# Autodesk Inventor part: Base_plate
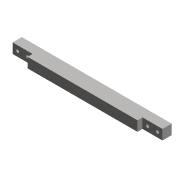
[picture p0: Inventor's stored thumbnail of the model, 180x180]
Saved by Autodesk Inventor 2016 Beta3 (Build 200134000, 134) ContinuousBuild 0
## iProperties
Created: 2016-02
Part Number: Base_plate
Material: Steel, Carbon
Document SubType Name: Modeling
Designer: Vertex
Density: 7.85 g/cm^3
Appearance: Semi-Polished
Mass: 1248.24 g
Surface Area: 308.183 cm^2
Volume: 159.012 cm^3
Author: Vertex
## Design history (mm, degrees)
sketch "Sketch1"
  geometry: L1 (0, 0)-(300, 0); L2 (300, 0)-(300, 20); L3 (300, 20)-(0, 20); L4 (0, 20)-(0, 0); L5 (0, 20)-(0, 0); L6 (40, 20)-(40, 0); L7 (300, 20)-(300, 0); L8 (260, 0)-(260, 20)
  constraints: 16 end point, 5 equal length, 1 horizontal, 1 perpendicular, 1 vertical
  dimensions: "d0" = 300 distance of L3.end L2.end; "d1" = 20 distance of L2.end L1.end; "d2" = 40 distance between parallel lines of L4 L6; "d3" = 40 distance between parallel lines of L2 L8
extrude "Extrusion1" new body sketch "Sketch1" distance "d4" = 20; taper "d5" = 0 deg
sketch "Sketch2"
  geometry: L1 (0, 0)-(300, 0); L2 (300, 0)-(300, 20); L3 (300, 20)-(0, 20); L4 (300, 20)-(0, 20) reference; L5 (0, 20)-(0, 0); L6 (0, 0)-(300, 0) reference; L7 (300, 20)-(300, 0); L8 (260, 0)-(260, 20); L9 (40, 20)-(40, 0)
  constraints: 8 end point, 4 point on line, 2 parallel, 1 perpendicular, 1 vertical
  dimensions: "d6" = 40 distance between parallel lines of L2 L8; "d7" = 40 distance between parallel lines of L5 L9
extrude "Extrusion2" join sketch "Sketch2" distance "d8" = 10; taper "d9" = 0 deg
workplane "Work Plane1"
chamfer "Chamfer1" distance "d28" = 1.5; stored, may be unused: second distance "d29" = 1.25, angle "d30" = 45 deg
hole "Hole3" diameter "d33" = 6; stored, may be unused: countersink angle "d37" = 90 deg, drill point angle "d39" = 118 deg; dims "d31" = 10, "d32" = 10, "d34" = 7.5, "d35" = 10, "d36" = 10, "d38" = 10
hole "Hole4" diameter "d42" = 6; stored, may be unused: countersink angle "d46" = 90 deg, drill point angle "d48" = 118 deg; dims "d40" = 30, "d41" = 10, "d43" = 7.5, "d44" = 10, "d45" = 10, "d47" = 10
mirror "Mirror2"
body "Solid1"
